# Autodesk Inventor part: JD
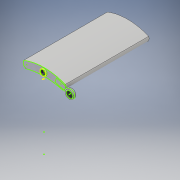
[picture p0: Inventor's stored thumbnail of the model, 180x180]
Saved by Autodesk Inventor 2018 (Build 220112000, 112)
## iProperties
Created: 2018-02
Part Number: JD
Material: Generic
Document SubType Name: Modeling
Designer: RinoyS
Density: 1 g/cm^3
Appearance: Default
Author: RinoyS
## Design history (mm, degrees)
sketch "Sketch1"
  geometry: L1 (9.337, 5.277)-(18.043, 2.612); L2 (17.031, -0.694)-(8.325, 1.971); L3 (8.325, 1.971)-(9.337, 5.277); C1 r 2.305 at (-0.058, 4.499); C2 r 3.112 at (20.292, 0.116); A1 r 2.944 centre (-13.114, 2.592) between (-15.476, 4.349) and (-13.718, -0.29); A2 r 51.753 centre (-0.092, -50.218) between (14.08, -0.442) and (-13.718, -0.29); A3 r 3.395 centre (12.983, 2.77) between (14.08, -0.442) and (16.114, 4.082); A4 r 42.618 centre (-0.016, -35.366) between (16.114, 4.082) and (-15.476, 4.349); 1 further point
  constraints: 8 point on circle, 6 centre point, 6 end point, 1 parallel
extrude "Extrusion1" new body sketch "Sketch1" distance "d0" = 63.8875; taper "d1" = 0 deg
extrude "Extrusion2" join sketch "Sketch1" stored distance "d2" = 2; taper "d3" = 0 deg
extrude "Extrusion3" join sketch "Sketch1" distance "d4" = 1; taper "d5" = 0 deg
sketch "Sketch2"
  geometry: C1 r 2.305 at (0, 0) reference; C2 r 1.81 at (0, 0); 1 further point
  constraints: 1 centre point, 1 coincident
extrude "Extrusion4" cut sketch "Sketch2" distance "d6" = 39.1; taper "d7" = 0 deg
sketch "Sketch3"
  geometry: C1 r 2.445 at (0, 0); 1 further point
  constraints: 1 centre point
extrude "Extrusion5" cut sketch "Sketch3" distance "d8" = 1; taper "d9" = 0 deg
workplane "Work Plane1"
body "Solid1"
